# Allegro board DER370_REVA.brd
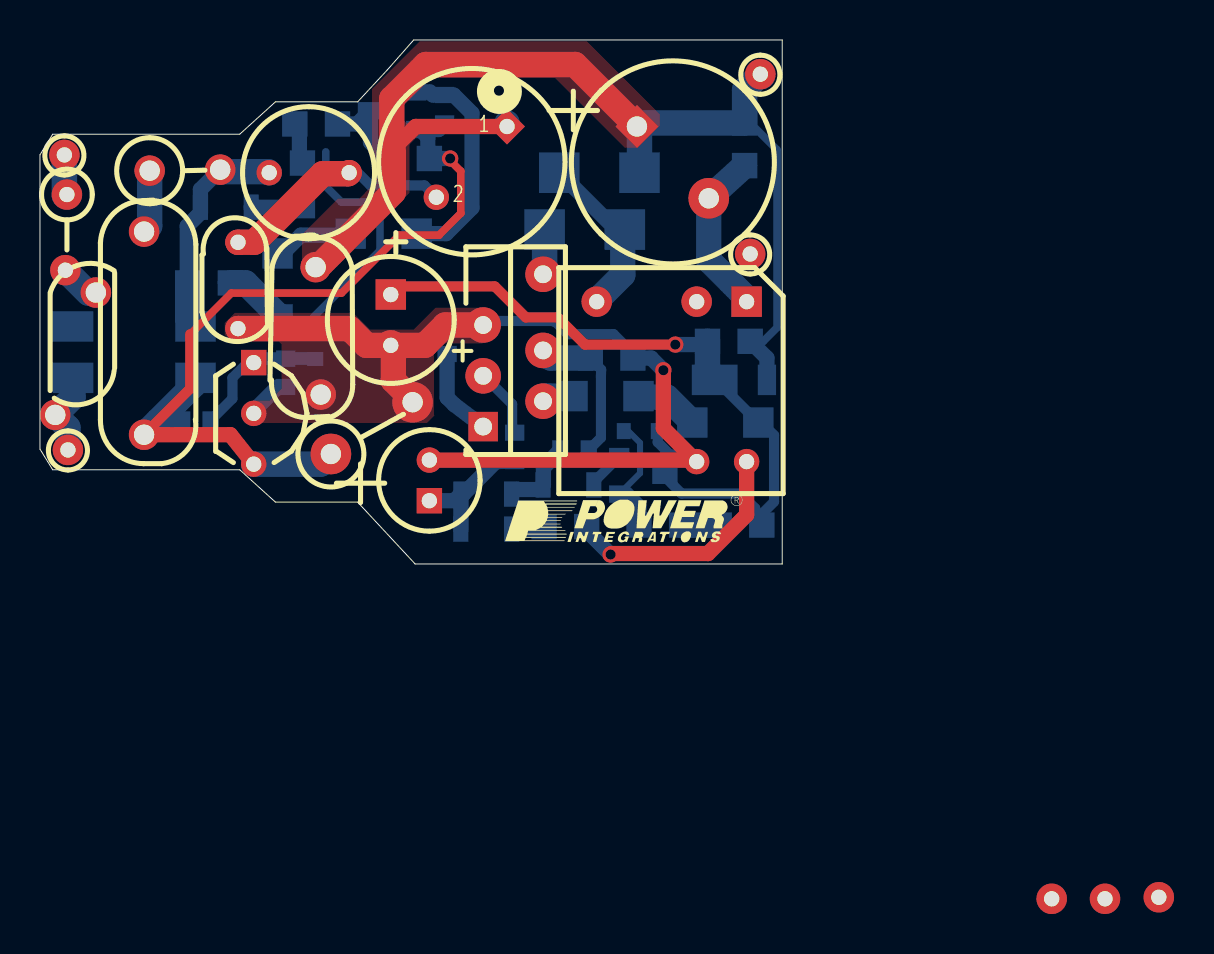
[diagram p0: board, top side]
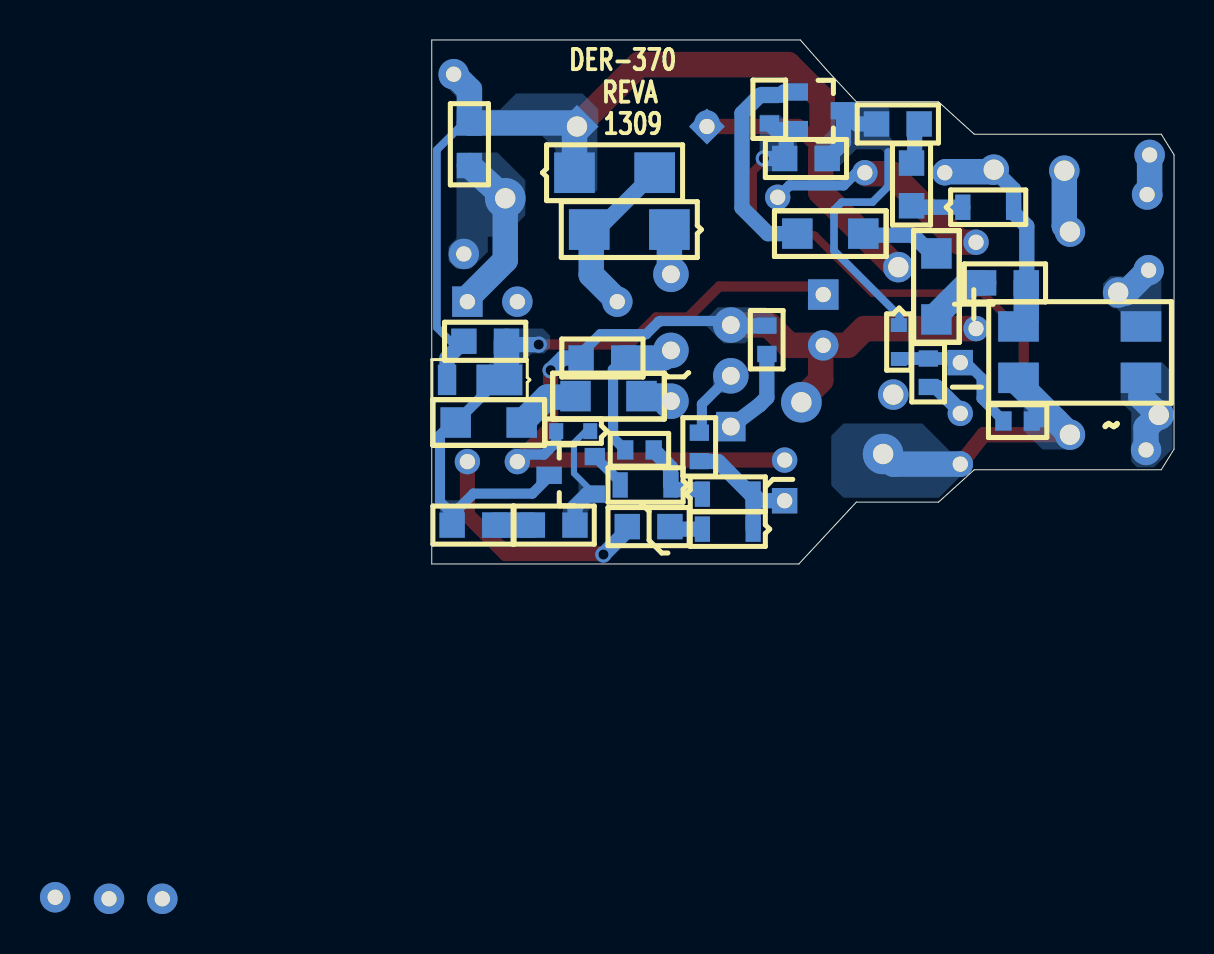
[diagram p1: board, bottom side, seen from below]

Outline 37.14 x 26.21 mm; copper layers: TOP, BOTTOM. Coordinates in mm from the lower left corner of the outline.
Outline path: 0,20.47 0,5.75 0.64,4.71 9.99,4.71 11.78,3.09 15.9,3.09 18.77,0 37.14,0 37.14,26.21 18.7,26.21 17.38,24.71 15.9,23.12 11.78,23.12 9.99,21.5 0.64,21.5 0,20.47

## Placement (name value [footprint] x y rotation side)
BR1  B10S-G  [PISMSOIC4]  1.65 9.31 90 bottom
C1  220 nF  [PINPCAPRAD500X260400040]  5.18 16.65 270 top
C2  100 pF  [PISMC0805]  7.39 14.06 0 bottom
C3  33 nF  [PISMC0805]  17.35 20.28 0 bottom
C4  10 nF  [PISMC0603]  8.54 7.15 180 bottom
C6  10 nF  [PI_NP_CAP250X200LS170D030]  9.91 16.09 270 top
C7  47 nF  [PINPCAPRAD500X240400040]  13.77 14.87 270 top
C8  2.2 uF  [PIPOLCAPCYLD250LS100030]  17.55 13.48 270 top
C10  4.7 uF  [PISMC0805]  27.54 10.3 0 bottom
C11  22  uF  [PIPOLCAPCLYD200LS80030]  19.48 3.16 90 top
C12  68 uF  [PIPOLCAPCYLD400LS200040]  29.87 21.88 315 top
D1  BAV19WS  [PISMSOD323]  10.57 17.85 180 bottom
D3  DFLR1600-7  [PISMDDFLR120012]  33.73 9.21 180 bottom
D5  US1D  [PISMDSMA]  25.25 16.73 0 bottom
D7  US1G  [PISMDSMA]  30 19.57 180 bottom
D8  BAV21WS-7-F  [PISMSOD323]  21.06 1.74 0 bottom
D9  BAV19WS  [PISMSOD323]  23.6 3.5 180 bottom
D10  BAV19WS  [PISMSOD323]  25.17 3.95 0 bottom
FR1  10  [PI14WVRESD100LS100D030]  1.35 18.48 270 top
J1  PCB Terminal 30 AWG  [PI_HOLE_30AWG]  36.05 24.5 0 top
J2  PCB Terminal 30 AWG  [PI_HOLE_30AWG]  35.54 15.51 0 top
L  PCB Terminal 30 AWG  [PI_HOLE_30AWG]  1.22 20.46 0 top
L1  820 uH  [PICHOKETOKINVD276H413LS158D030]  15.47 19.57 180 top
L2  1.5 mH  [PI_CHOKE_450HX375LS197D030]  23.37 21.88 225 top
N  PCB Terminal 30 AWG  [PI_HOLE_30AWG]  1.4 5.7 0 top
NOREF  -  []  -228.6 -140.07 0 top
NOREF#2  -  []  18.7 26.21 0 top
NOREF#3  -  []  37.14 0 90 top
NOREF#4  -  []  -150.78 58.95 0 top
NOREF#5  -  []  0 4.71 90 top
NOREF#6  -  []  23.27 1.08 0 top
NOREF#7  -  []  0 5.75 0 top
Q1  MMBTA06LT1G  [PISMSOT23132]  18.82 21.73 270 bottom
Q2  STQ2NK60ZR-AP  [PIT092100]  10.7 10.07 270 top
Q3  FMMT458TA  [PISMSOT23132]  28.98 5.37 90 bottom
R1  1 k  [PI12WRESD180LS675D040]  5.49 19.67 0 top
R2  270  [PI2WVRESD180LS200040]  14.56 5.5 28.7 top
R3  91 k  [PISMR1206]  11.89 12.23 90 bottom
R4  130 k  [PISMR1206]  15.55 16.53 0 bottom
R5  30 k  [PISMR0603]  20.25 23.46 270 bottom
R6  2 M  [PISMR0805]  13.13 20.06 270 bottom
R7  2 M  [PISMR0805]  14.89 22.01 180 bottom
R9  300 k  [PISMR0603]  12.3 10.28 270 bottom
R12  510 k  [PISMR0805]  35.54 11.14 180 bottom
R13  2 M  [PISMR1206]  35.94 7.08 180 bottom
R14  1.8 M  [PISMR1206]  29.95 8.4 180 bottom
R17  24.9 k  [PISMR0603]  20.37 11.93 270 bottom
R18  464 k  [PISMR0603]  23.75 6.57 270 bottom
R19  6.2 k  [PISMR0603]  26.04 5.7 0 bottom
R20  51  [PISMR0805]  27.36 1.87 180 bottom
R22  470 k  [PISMR0805]  33.99 1.95 0 bottom
R23  470 k  [PISMR0805]  32.11 1.95 180 bottom
R24  39 k  [PISMR0805]  35.26 22.06 270 bottom
RV1  250 Vac  [PIDISC350X160LS210X140040]  4.32 13.55 270 top
T1  EE10  [PI_BOBBIN_EE10_8P]  35.36 13.12 270 top
U1  LYT4321E  [PIICESIP76TH]  22.18 6.87 90 top
VR1  DZ2S15000L  [PI_SM_D_SSMINI2P]  13.77 11.95 270 bottom
VR2  DZ2S200M0L  [PI_SM_D_SSMINI2P]  29.21 6.64 0 bottom

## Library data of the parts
BR1 = DIODE BRIDGE_~~+-
C1 C6 = CAP NP: room: 1
C2-C4 C7 C10 = CAP NP
C8 = CAP POL: alternate symbols: (pipolcapcyld250ls100030h)
C11 C12 = CAP POL
D1 D3 D5 D7-D10 = DIODE
FR1 = R: alternate symbols: (pi14wvresd100ls200d030,pi14wresd100ls400d030,pi14wresd100ls500d030)
J1 J2 L N = TERM_1Pin
L1 = INDUCTOR
L2 = INDUCTOR1-2
Q1 Q3 = NPN_BEC
Q2 = FET_N_GDS
R1 = R: alternate symbols: (pi2wvresd180ls250040,pi12wresd180ls675d040); room: 1
R2 = R: alternate symbols: (pi2wvresd180ls250040,pi12wresd180ls675d040)
R3-R7 R9 R12-R14 R17-R20 R22-R24 = R
RV1 = VARISTOR
T1 = BEE16_8P/GENERIC
U1 = LNK40X_eSIP
VR1 VR2 = DIODE_ZENER

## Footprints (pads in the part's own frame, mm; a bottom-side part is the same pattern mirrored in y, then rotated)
PI2WVRESD180LS200040
  round 2.032 hole 1.016: 1(0,0) 2(4.831,0.307)
PI12WRESD180LS675D040
  round 1.524 hole 1.016: 1(0,0) 2(3.531,0.051)
PI14WVRESD100LS100D030
  round 1.524 hole 0.762: 1(0,0) 2(3.785,-0.076)
PI_BOBBIN_EE10_8P
  rect 1.524x1.524 hole 0.762: 1(0,0)
  round 1.524 hole 0.762: 2(0,-2.499) 3(29.794,20.625) 4(0,-7.501) 5(29.87,17.932) 6(29.87,15.265)
  round 1.27 hole 0.762: 7(8.001,-2.499) 8(8.001,0)
PI_CHOKE_450HX375LS197D030
  rect 1.27x1.27 hole 0.762: 1(0,0)
  round 1.27 hole 0.762: 2(5.004,0)
PI_HOLE_30AWG
  round 1.524 hole 0.762: 1(0,0)
PI_NP_CAP250X200LS170D030
  round 1.27 hole 0.762: 1(0,0) 2(4.318,0)
PI_SM_D_SSMINI2P
  rect 0.699x0.8 smd: 1(0,0) 2(1.699,0)
PICHOKETOKINVD276H413LS158D030
  round 1.27 hole 0.762: 1(0,0) 2(4,0)
PIDISC350X160LS210X140040
  round 1.524 hole 1.016: 1(-0.025,-1.524) 2(6.096,-3.556)
PIICESIP76TH
  rect 1.473x1.473 hole 0.889: 1(0,0)
  round 1.778 hole 0.889: 2(1.27,-2.997) 3(2.54,0) 4(3.81,-2.997) 5(5.08,0) 7(7.62,-2.997)
PINPCAPRAD500X240400040
  round 1.524 hole 1.016: 1(0.025,0.025) 2(6.401,0.279)
PINPCAPRAD500X260400040
  round 1.524 hole 1.016: 1(0.025,0.025) 2(10.185,0.025)
PIPOLCAPCLYD200LS80030
  rect 1.27x1.27 hole 0.762: 1(0,0)
  round 1.27 hole 0.762: 2(2.032,0)
PIPOLCAPCYLD250LS100030
  rect 1.524x1.524 hole 0.762: 1(0,0)
  round 1.524 hole 0.762: 2(2.54,0)
PIPOLCAPCYLD400LS200040
  rect 1.524x1.524 hole 1.016: 1(0,0)
  round 2.032 hole 1.016: 2(5.08,0)
PISMC0603
  rect 0.813x0.965 smd: 1(0,0) 2(1.422,0)
PISMC0805
  rect 1.27x1.27 smd: 1(0,0) 2(2.134,0)
PISMDDFLR120012
  rect 2.286x1.524 smd: 1(-0.025,0)
  rect 0.914x1.524 smd: 2(-2.642,0)
PISMDSMA
  rect 2.032x2.032 smd: 1(0,0) 2(4.013,0)
PISMR0603
  rect 0.813x0.965 smd: 1(0,0) 2(1.422,0)
PISMR0805
  rect 1.27x1.27 smd: 1(0,0) 2(2.134,0)
PISMR1206
  rect 1.524x1.524 smd: 1(0,0) 2(3.302,0)
PISMSOD323
  rect 0.762x1.27 smd: 1(0,0) 2(2.54,0)
PISMSOIC4
  rect 1.524x2.032 smd: 1(0,0) 2(2.57,0) 3(2.57,6.129) 4(0,6.129)
PISMSOT23132
  rect 0.864x1.016 smd: 1(-1.88,0) 2(0,0)
  rect 0.864x1.27 smd: 3(-0.94,2.286)
PIT092100
  rect 1.27x1.27 hole 0.762: 1(0,0)
  round 1.27 hole 0.762: 2(2.54,0) 3(5.08,0)

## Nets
PK_DET: C8.1 D3.1 Q3.3(COLLECTOR) R12.2 R13.1 R22.2
N2040939: C6.2 C7.2 C8.2 C10.2 C11.2 Q2.2(D) R2.2 R9.2 R17.1 T1.7 U1.5(S) VR2.2
N2229506: BR1.4 C1.2 C3.2 C4.2 Q1.2(EMITTER) Q2.3(S) R2.1 R5.2
N2232323: BR1.1 N.1 RV1.2
N2487375: BR1.2 FR1.2 RV1.1
N2491459: C10.1 R19.2 U1.4(BP)
N2492720: D5.1 U1.7(D)
N2492766: R17.2 U1.1(R)
N2493445: C12.2 J2.1 R24.2 T1.1
N2532048: R18.1 U1.3(FB)
N2538393: BR1.3 C2.1 D1.2 L1.2 R1.2
N2541951: R14.2 U1.2(V)
N2543404: C7.1 C12.1 D3.2 D7.1 J1.1 L2.1 R12.1 R24.1
N3718814: C11.1 D8.1 D9.2 R18.2
N3765694: D9.1 D10.1 R19.1
N3776097: C6.1 L1.1 L2.2
N3815881: FR1.1 L.1
N3840471: R13.2 R14.1
N3915236: C4.1 Q2.1(G) R9.1 VR1.2
N3915298: R3.2 R4.1
N3915302: C3.1 Q1.3(COLLECTOR) R7.1 VR1.1
N3915322: Q1.1(BASE) R4.2 R5.1
N3915464: C2.2 R3.1
N3918720: C1.1 R1.1
N3927142: Q3.1(BASE) R23.2 VR2.1
N3927314: D10.2 Q3.2(EMITTER)
N3985304: R20.1 T1.8
N4004994: D5.2 D7.2 T1.4
N4015758: R22.1 R23.1
N4024101: R6.1 R7.2
N4030121: D8.2 R20.2
N39152881: D1.1 R6.2

Pads without a net: T1 2 3 5 6

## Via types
v1: diameter 0.813, hole 0.508, TOP to BOTTOM, 4 vias

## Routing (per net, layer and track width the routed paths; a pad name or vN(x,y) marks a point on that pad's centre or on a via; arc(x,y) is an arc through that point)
PK_DET: length 34.6
  TOP w0.508: C8.1 17.96,13.88 22.76,13.88 24.31,12.33 25.91,12.33 27.27,10.98 v1(31.79,10.98)
  BOTTOM w0.508: 31.37,4.54 Q3.3 31.27,4.36 32.11,3.52 35.05,3.52 35.79,2.79 35.79,2.17 ; D3.1 33.81,9.21 R13.1 36.1,7.08 36.73,6.44 36.73,3.11 35.79,2.17 ; 35.79,2.17 35.97,2.15 R22.2
  BOTTOM w0.762: R12.2 33.24,10.98 v1(31.79,10.98)
  BOTTOM w1.27: D3.1 33.4,9.57 R12.2
N2040939: length 52.7
  TOP w0.762: C11.2 32.78,5.2 ; 32.78,5.2 31.19,6.79 v1(31.19,9.69) ; 32.78,5.2 T1.7
  TOP w1.27: 18.87,7.79 18.87,7.99 17.68,9.18 17.68,10.81 C8.2 ; C6.2 15.5,11.78 16.33,10.94 C8.2 ; C8.2 19.26,10.94 20.27,11.95 U1.5
  BOTTOM w0.508: T1.7 32.5,5.48 31.53,5.48 30.91,6.09 VR2.2 ; U1.5 22.38,12.16 25.68,12.16 25.71,12.13 25.78,12.13 26.41,11.5 28.7,11.5 29.54,10.66 29.54,10.22 29.55,10.23 C10.2
  BOTTOM w0.762: v1(31.19,9.69) 30.58,10.3 C10.2 ; Q2.2 10.7,7.66 11.89,8.85 R9.2 ; U1.5 21.59,11.9 R17.1
N2229506: length 44.8
  TOP w0.381: v1(20.53,20.28) 20.53,20.18 21.06,19.65 21.06,17.54 19.97,16.45 17.99,16.45 15.09,13.55 9.58,13.55 7.52,11.5
  TOP w0.508: 20.37,20.28 v1(20.53,20.28) ; C1.2 7.52,8.78 7.52,11.5
  TOP w0.762: C1.2 9.53,6.47 Q2.3
  BOTTOM w0.635: C4.2 5.95,7.15 5.92,7.18
  BOTTOM w0.762: 19.03,21.73 19.94,21.73 R5.2 ; 19.03,21.73 Q1.2 ; 19.03,21.73 19.41,21.35 19.41,20.36 C3.2 v1(20.53,20.28)
  BOTTOM w1.27: BR1.4 7.78,9.04 C1.2 ; Q2.3 14.05,4.99 R2.1
N2232323: length 4.2
  BOTTOM w1.27: N.1 1.4,6.82 RV1.2 1.65,8.35 BR1.1
N2487375: length 2
  BOTTOM w1.27: FR1.2 2.42,13.55 RV1.1
N2491459: length 7.6
  BOTTOM w0.508: R19.2 28.07,6.31 28.07,9.39 28.08,9.72 C10.1
  BOTTOM w1.27: C10.1 25.55,10.3 U1.4
N2492720: length 2.3
  BOTTOM w1.27: D5.1 25.25,14.57 U1.7
N2492766: length 4.5
  BOTTOM w0.762: R17.2 20.37,8.33 20.73,7.97 U1.1
N2493445: length 9
  TOP w1.27: 33.58,18.41 C12.2
  BOTTOM w0.762: 35.54,12.94 T1.1
  BOTTOM w1.27: 33.48,18.31 R24.2 ; 33.48,18.31 C12.2 33.46,15.19 35.36,13.3 T1.1 ; 33.48,18.31 33.65,18.48
N2532048: length 3.5
  BOTTOM w0.508: R18.1 23.62,6.7 23.62,8 22.21,9.41 U1.3
N2538393: length 11.2
  BOTTOM w0.381: R1.2 9.12,19.62
  BOTTOM w0.762: C2.1 7.37,14.09 7.37,16.91 8.03,17.57 D1.2 8.03,18.74 R1.2
  BOTTOM w1.27: L1.2 11.42,19.62 9.12,19.62 ; C2.1 7.39,12.27 BR1.3
N2541951: length 1.6
  BOTTOM w1.27: U1.2 25.43,8.4 R14.2
N2543404: length 56.6
  TOP w0.762: 17.6,20.69 18.8,21.88 L2.1
  TOP w1.27: C12.1 26.77,24.98 19.31,24.98 17.6,23.28 17.6,20.69 17.68,20.61 17.68,18.61 13.92,14.85 C7.1
  BOTTOM w0.381: R24.1 35.54,22.06 36.88,20.72 36.88,11.83 36.2,11.14 R12.1
  BOTTOM w0.762: D3.2 36.38,10.3 R12.1
  BOTTOM w1.27: C12.1 30,21.76 D7.1 ; C12.1 29.87,21.96 ; C12.1 30.05,22.06 R24.1 35.26,23.71 J1.1 36.15,24.4 ; 23.37,22.06 L2.1
N3718814: length 6.9
  BOTTOM w0.762: D9.2 21.19,3.5 22.81,5.12 R18.2 ; D9.2 D8.1 ; D9.2 20.73,3.16 19.79,3.16 19.66,3.1 C11.1
N3765694: length 3.9
  BOTTOM w0.762: R19.1 25.19,4.81 25.19,3.97 D10.1 24.95,3.72 23.83,3.72 D9.1
N3776097: length 11.9
  TOP w1.27: L1.1 15.42,19.52 14.15,19.52 10.72,16.09 C6.1
  BOTTOM w0.508: L2.2 19.24,18.94 16.54,18.94 15.9,19.57 L1.1
N3815881: length 2.2
  BOTTOM w0.762: 1.25,18.4 1.32,18.48 FR1.1
  BOTTOM w1.27: 1.25,18.4 1.22,18.43 L.1
N3840471: length 3.4
  BOTTOM w0.508: 31.24,8.35 31.31,8.41 31.37,8.35
  BOTTOM w1.27: R14.1 30,8.35 31.37,8.35 R13.2
N3915236: length 7.2
  BOTTOM w0.508: Q2.1 10.39,10.07 9.63,9.31 9.63,8.27 8.54,7.18 C4.1
  BOTTOM w0.635: VR1.2 13.75,10.28 R9.1 10.9,10.28
  BOTTOM w0.762: 10.9,10.28 Q2.1
N3915298: length 4
  BOTTOM w0.762: R4.1 14.96,16.45 13.06,16.45 12.14,15.53 R3.2
N3915302: length 16.7
  BOTTOM w0.381: VR1.1 13.72,12 13.72,12.38 17.01,15.68 17.01,17.72 16.63,18.1 15.09,18.1 14.3,18.89 14.3,20.61
  BOTTOM w0.762: C3.1 16.54,21.1 Q1.3 15.88,22.01 R7.1
N3915322: length 11.3
  BOTTOM w0.762: Q1.1 19.51,23.61 19.66,23.46 R5.1 20.7,23.46 21.62,22.55 21.62,17.82 20.32,16.53 R4.2
N3915464: length 3.3
  BOTTOM w1.27: C2.2 10.29,14.06 11.89,12.46 R3.1
N3918720: length 3.2
  BOTTOM w1.27: R1.1 5.49,16.91 C1.1
N3927142: length 6.2
  BOTTOM w0.305: VR2.1 29.44,6.64 30.03,6.06 30.03,4.54 Q3.1
  BOTTOM w0.762: Q3.1 29.34,3.5 29.97,2.86 R23.2
N3927314: length 1.9
  BOTTOM w0.508: D10.2 27.71,4.1 Q3.2
N3985304: length 12.2
  TOP w0.762: T1.8 35.36,2.45 33.43,0.52 28.6,0.52 v1(28.55,0.47)
  BOTTOM w0.762: R20.1 27.36,1.67 v1(28.55,0.47)
N4004994: length 8.6
  BOTTOM w0.762: D5.2 28.83,16.73 D7.2
  BOTTOM w1.27: D5.2 29.16,16.63 29.16,14.47 27.86,13.16 T1.4
N4015758: length 1.9
  BOTTOM w1.27: R23.1 R22.1
N4024101: length 2.1
  BOTTOM w0.762: R7.2 12.98,21.78 12.98,20.21 R6.1
N4030121: length 3.5
  BOTTOM w0.508: D8.2 23.68,1.82 25.02,1.82 25.1,1.74 25.17,1.74 25.3,1.87
  BOTTOM w0.762: R20.2 25.1,1.74 D8.2
N39152881: length 2.6
  BOTTOM w0.762: R6.2 13.06,17.85 D1.1

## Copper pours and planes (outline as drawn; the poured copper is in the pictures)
PK_DET on BOTTOM: 34.01,11.78 31.57,11.78 31.22,11.42 31.22,10.84 31.52,10.53 32.13,10.53 32.59,10.07 32.59,8.42 34.88,8.42 34.9,8.45 34.9,9.97 34.32,9.97 34.01,10.28
PK_DET on BOTTOM: 35.56,3.19 36.71,3.19 36.73,3.16 36.73,2.4 36.58,2.25 35.56,2.25 35.51,2.3 35.51,3.04 35.46,3.09
N2040939 on TOP: 19.71,10.51 20.25,11.04 22.15,11.04 22.35,11.24 22.35,12.54 22.08,12.82 19.79,12.82 18.7,11.72 16.51,11.72 15.67,12.56 9.76,12.56 9.25,12.05 9.25,11.47 9.59,11.13 11.95,11.13 12.09,10.99 12.09,8.78 11.48,8.17 10.67,8.17 10.65,8.14 10.65,6.97 10.72,7.05 19.36,7.05 19.74,7.43 19.71,7.46
N2040939 on BOTTOM: 23.29,12.33 23.29,12.39 22.84,12.84 20.42,12.84 19.92,12.33 19.92,11.52 20.86,11.52 20.88,11.55 20.96,11.55 21.47,11.04 22.53,11.04 23.5,12 23.52,12 23.52,12.31 23.5,12.33
N2040939 on BOTTOM: 32.26,4.92 32.26,5.12 32.16,5.22 31.52,5.22 31.4,5.35 31.4,5.93 31.45,5.88 33,5.88 33.35,5.53 33.35,5.27 33,4.92
N2229506 on BOTTOM: 7.52,6.67 7.52,8.02 7.42,8.12 6.78,8.12 5.36,6.7 5.36,5.76 5.39,5.73 6.58,5.73
N2229506 on BOTTOM: 10.52,5.65 11.23,5.65 12.6,7.03 16.54,7.03 17.15,6.42 17.15,3.93 16.54,3.32 11.76,3.32 10.57,4.51 10.57,4.79 10.37,4.99 10.37,5.5
N2229506 on BOTTOM: 19.74,22.47 20.73,22.47 20.73,20.49 20.6,20.36 20.6,19.88 20.37,19.65 18.9,19.65 18.85,19.7 18.85,20.89 18.87,20.92 18.87,21.07 18.65,21.3 18.34,21.3 18.32,21.33 18.32,22.16 19.43,22.16
N2232323 on BOTTOM: 2.67,10.07 2.67,8.12 2.14,7.58 2.14,5.12 1.86,4.84 0.99,4.84 0.08,5.76 0.08,9.57 0.59,10.07
N2487375 on BOTTOM: 0.64,11.14 0.64,14.77 0.89,15.03 1.86,15.03 2.49,14.39 3.18,14.39 3.56,14.01 3.56,13.27 3.08,12.79 2.87,12.79 2.67,12.59 2.67,11.17 2.69,11.14
N2493445 on BOTTOM: 33.53,16.37 34.34,16.37 34.34,15.66 34.32,15.64 35.18,14.77 35.92,14.77 36.27,15.13 36.3,15.13 36.3,15.89 35.91,16.28 35.91,20.53 35.84,20.59 33.86,20.59 32.46,19.19 32.46,17.44
N2543404 on TOP: 13.11,14.72 13.11,16.47 14.91,18.28 15.98,18.28 16.61,18.91 16.61,23.76 19,26.15 27.36,26.15 31.02,22.49 31.02,21.94 29.9,20.82 29.26,20.82 25.76,24.32 19.59,24.32 18.24,22.98 18.24,22.14 18.29,22.09 18.57,22.09 19,21.66 19,21.5 18.49,21 18.49,18.58 14.51,14.59 13.24,14.59
N2543404 on BOTTOM: 28.81,21.99 28.81,22.75 29.59,23.54 32.92,23.54 33.73,22.72 34.27,22.72 34.62,23.08 34.62,23.99 35.51,24.88 36.12,24.88 36.65,24.35 36.65,24.12 35.87,23.33 35.87,21.55 35.79,21.48 31.68,21.48 30.97,20.77 30.97,18.63 30.99,18.61 28.96,18.61 28.86,18.71 28.86,21.94
N3915302 on BOTTOM: 17.17,23.1 17.17,21.73 17.96,20.94 17.96,19.67 16.74,19.67 16.74,19.9 15.9,20.74 14.66,20.74 14.46,20.54 14.2,20.54 14.12,20.61 14.12,21.28 14.25,21.4 14.25,22.77 14.58,23.1
N3927142 on BOTTOM: 30.58,2.56 30.58,2.81 29.8,3.6 29.8,4.31 29.59,4.31 28.86,3.57 28.86,3.11 29.34,2.63 29.34,2.48 29.54,2.28 30.46,2.28 30.51,2.33 30.51,2.48

Small or netless copper shapes (teardrops, artwork), in the pictures only: 1 on BOTTOM

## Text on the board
Ref Des/Silkscreen Bottom: 1309 | REVA | DER-370
PEN17: PLEASE DELETTE THESE PINS | 13   MATERIAL FR4 COPPER 2oz THICKNESS 0.031"
User.5: FIGURE | SIZE | 20.0 | 30.0 | 35.0 | 40.0 | DRILL CHART: TOP to BOTTOM | ALL UNITS ARE IN MILS | PLATED | QTY | 4 | 27 | 6 | 12
